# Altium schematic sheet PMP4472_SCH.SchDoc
size 431 x 279 mm; Date: Not shown in title block; ApprovedBy: Not shown in title block; CheckedBy: Not shown in title block; Author: Not shown in title block; CompanyName: Not shown in title block; Engineer: Not shown in title block; Organization: Not shown in title block; Address1: Not shown in title block; Address2: Not shown in title block; Address3: Not shown in title block; Address4: Not shown in title block; DocumentNumber: 1; Revision: Use project parameter SCH_Rev; SheetNumber: 1; SheetTotal: 1; PageSetup: Record=PageOptions¦CenterHorizontal=True¦CenterVertical=True¦PrintScale=1.00¦XCorrection=1.00¦YCorrection=1.00¦PrintKind=0¦BorderSize=5000000¦LeftOffset=0¦BottomOffset=0¦Orientation=2¦PaperLength=1000¦PaperWidth=1000¦Scale=100¦PaperSource=15¦PrintQuality=600¦MediaType=1¦DitherType=10¦PaperKind=Letter¦PrintScaleMode=1
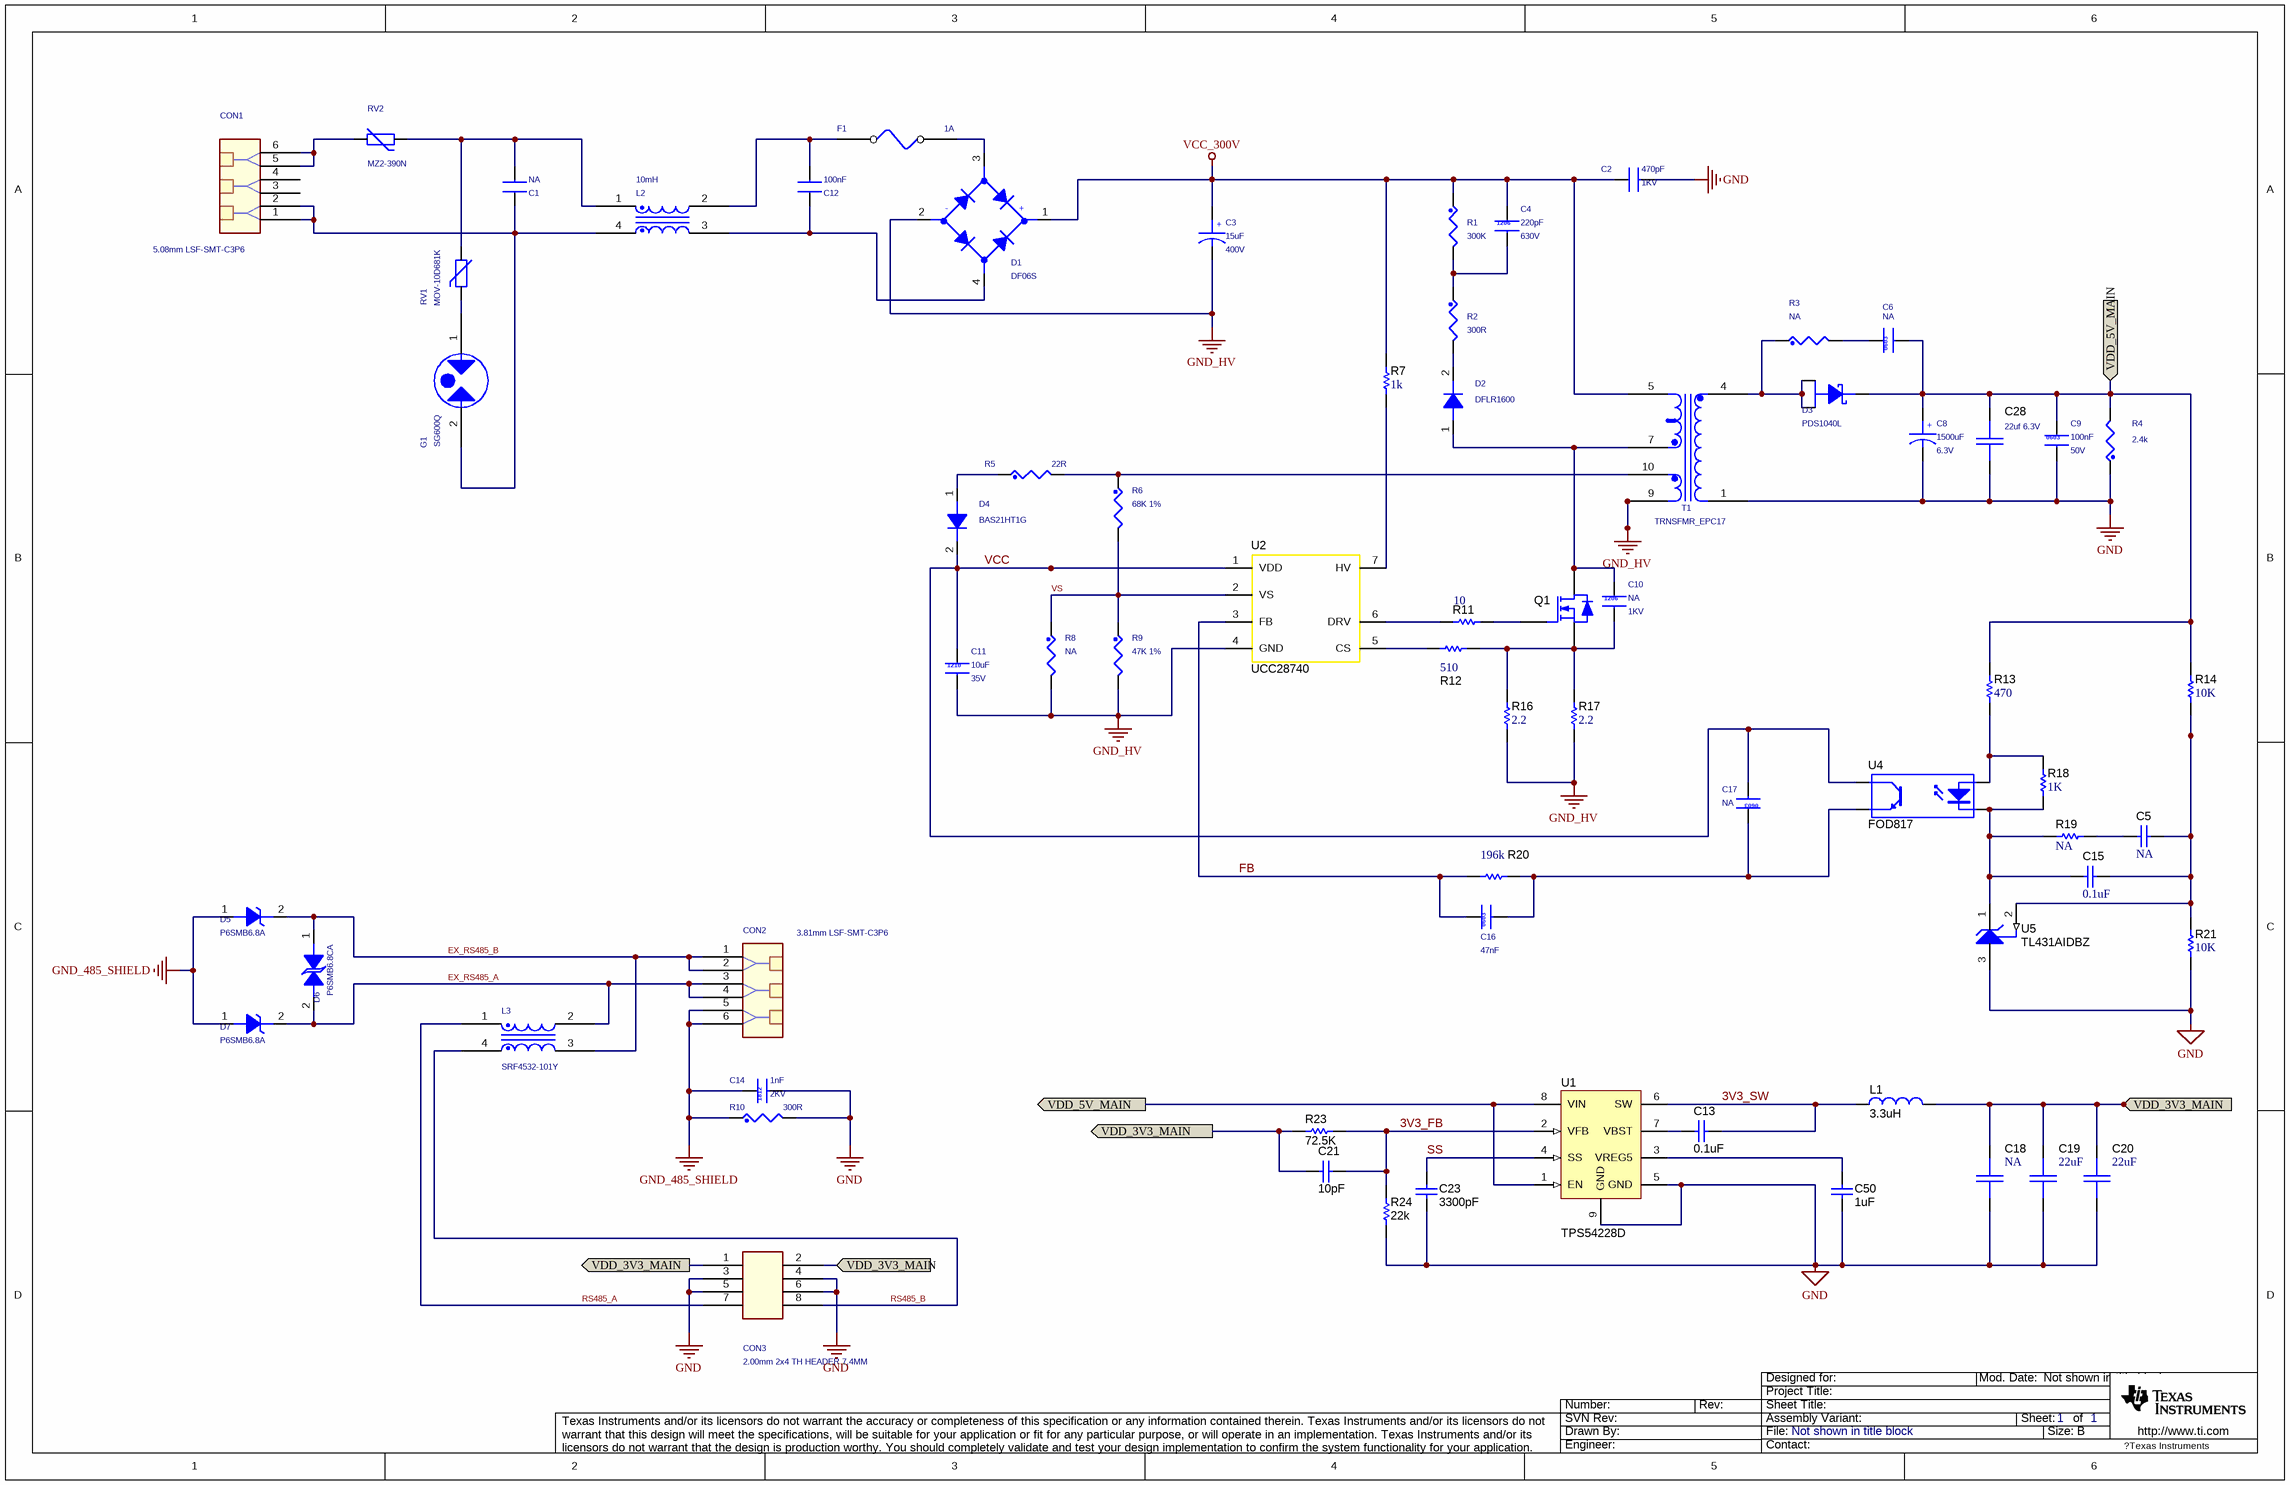
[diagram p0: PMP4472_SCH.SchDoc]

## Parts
C1  NA  [CAPRR_15D24_17D0X6D0X12D0]
C2  470pF  Voltage: 1KV  [CAPRR_10D16_9D5X7D0X9D5]
C3  15uF  Voltage: 400V  [CAPAE1000X1600_TH]
C4  220pF  Voltage: 630V  [C1206]
C5  value NA  [0603]  (hidden comment: Cap)
C6  NA  [C0603]
C8  1500uF  Voltage: 6.3V  [CAPAE1000X1600_TH]
C9  100nF  Voltage: 50V  [C0603]
C10  NA  Voltage: 1KV  [C1206]
C11  10uF  Voltage: 35V  [C1210]
C12  100nF  [CAPRR_15D24_17D0X6D0X12D0]
C13  ValueDisplayed: 0.1uF  [0603]  (hidden comment: 06031C331JAT2A)
C14  1nF  Voltage: 2KV  [C1812]
C15  value 0.1uF  [0603]  (hidden comment: Cap)
C16  47nF  [C0603]
C17  NA  [C0603]
C18  NA  [C1206]
C19  22uF  [C1206]
C20  22uF  [C1206]
C21  ValueDisplayed: 10pF  [0603]  (hidden comment: 06031C331JAT2A)
C23  ValueDisplayed: 3300pF  [0603]  (hidden comment: 06031C331JAT2A)
C28  22uf 6.3V  [C1206]
C50  ValueDisplayed: 1uF  [0603]  (hidden comment: 06031C331JAT2A)
CON1  5.08mm LSF-SMT-C3P6  [CON_LSF-SMT-5D08-C3P6-180]
CON2  3.81mm LSF-SMT-C3P6  [CON_LSF-SMT-3D81-C3P6-180]
CON3  2.00mm 2x4 TH HEADER 7.4MM  [CON_2D00_2X4_TH]
D1  DF06S  [DIODE_DFS]
D2  DFLR1600  [POWERDI123]
D3  PDS1040L  [POWERDI5]
D4  BAS21HT1G  [SOD-323]
D5  P6SMB6.8A  [SMB]
D6  P6SMB6.8CA  [SMB]
D7  P6SMB6.8A  [SMB]
F1  1A  [F5D08_8D5X4D0X8D0MM]
G1  SG600Q  [G4532]
L1  3.3uH  [Inductor 744778003]
L2  10mH  [L16D0X12D0X17D5MM]
L3  SRF4532-101Y  [L4D5X3D2X2D8MM]
Q1  (no value)  [TO-251AB]
R1  300K  [R1206]
R2  300R  [R1206]
R3  NA  [R0805]
R4  2.4k  [R1206]
R5  22R  [0603]
R6  68K 1%  [0603]
R7  value 1k  [0805]  (hidden comment: Res1)
R8  NA  [0603]
R9  47K 1%  [0603]
R10  300R  [R1206]
R11  value 10  [0603]  (hidden comment: Res1)
R12  value 510  [0603]  (hidden comment: Res1)
R13  value 470  [0603]  (hidden comment: Res1)
R14  value 10K  [0603]  (hidden comment: Res1)
R16  value 2.2  [0805]  (hidden comment: Res1)
R17  value 2.2  [0805]  (hidden comment: Res1)
R18  value 1K  [0603]  (hidden comment: Res1)
R19  value NA  [0603]  (hidden comment: Res1)
R20  value 196k  [0603]  (hidden comment: Res1)
R21  value 10K  [0603]  (hidden comment: Res1)
R23  value 72.5K  [0603]  (hidden comment: CRCW06031K00FKEA)
R24  value 22k  [0603]  (hidden comment: CRCW06031K00FKEA)
RV1  MOV-10D681K  [MOV-10D]
RV2  MZ2-390N  [PTC-T5MMD10MM]
T1  TRNSFMR_EPC17  [EPC17]
U1  TPS54228D  [DDA-8]
U2  UCC28740  [SOIC-7]
U4  FOD817  [OPTOCOUPLER]
U5  TL431AIDBZ  [SOT-23]

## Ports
VDD_3V3_MAIN, VDD_5V_MAIN

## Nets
GND: C2.2 C8.2 C9.2 C14.2 C18.1 C19.1 C20.1 C23.2 C28.1 C50.2 CON3.3 CON3.4 CON3.5 CON3.6 R4.1 R10.2 R21.1 R24.1 T1.1(OUT1_N) U1.5(GND) U1.9(GND) U5.3(ANODE)
GND_485_SHIELD: C14.1 CON2.5 CON2.6 D5.1(ANODE) D7.1(ANODE) R10.1
GND_HV: C3.2 C11.2 D1.2(DC_OUT_MINUS) R8.2 R9.2 R16.1 R17.1 T1.9(OUT1_N) U2.4(GND)
VCC_300V: C2.1 C3.1 C4.1 D1.1(DC_OUT_PLUS) R1.1 R7.2 T1.5(IN1)
3V3_FB: C21.1 R23.2 R24.2 U1.2(VFB)
3V3_SW: C13.1 L1.1 U1.6(SW)
EX_RS485_A: CON2.3 CON2.4 D6.2 D7.2(CATHODE) L3.2
EX_RS485_B: CON2.1 CON2.2 D5.2(CATHODE) D6.1 L3.3
FB: C16.1 R20.2 U2.3(FB)
RS485_A: CON3.7 L3.1
RS485_B: CON3.8 L3.4
SS: C23.1 U1.4(SS)
VCC: C11.1 C17.2 D4.2(K) U2.1(VDD) U4.4(C)
VDD_3V3_MAIN: C18.2 C19.2 C20.2 C21.2 CON3.1 CON3.2 L1.2 R23.1 ; port VDD_3V3_MAIN
VDD_5V_MAIN: C6.2 C8.1 C9.1 C28.2 D3.3(CATHODE) R4.2 R13.2 R14.2 U1.1(EN) U1.8(VIN) ; port VDD_5V_MAIN
VS: R6.2 R8.1 R9.1 U2.2(VS)
NetC1_1: C1.1 CON1.1 CON1.2 G1.2 L2.4
NetC1_2: C1.2 L2.1 RV1.1 RV2.2
NetC4_2: C4.2 R1.2 R2.1
NetC5_1: C5.1 C15.1 R14.1 R21.2 U5.2(REF)
NetC5_2: C5.2 R19.1
NetC6_1: C6.1 R3.2
NetC10_1: C10.1 D2.1(A) Q1.2(D) T1.7(IN2)
NetC10_2: C10.2 Q1.3(S) R12.2 R16.2 R17.2
NetC12_1: C12.1 D1.4(AC_IN_2) L2.3
NetC12_2: C12.2 F1.1 L2.2
NetC13_2: C13.2 U1.7(VBST)
NetC15_2: C15.2 R18.1 R19.2 U4.2(K) U5.1(CATHODE)
NetC16_2: C16.2 C17.1 R20.1 U4.3(E)
NetC50_1: C50.1 U1.3(VREG5)
NetCON1_5: CON1.5 CON1.6 RV2.1
NetD1_3: D1.3(AC_IN_1) F1.2
NetD2_2: D2.2(K) R2.2
NetD3_1: D3.1(ANODE1) D3.2(ANODE2) R3.1 T1.4(OUT2_P)
NetD4_1: D4.1(A) R5.1
NetG1_1: G1.1 RV1.2
NetQ1_1: Q1.1(G) R11.2
NetR5_2: R5.2 R6.1 T1.10(OUT1_P)
NetR7_1: R7.1 U2.7(HV)
NetR11_1: R11.1 U2.6(DRV)
NetR12_1: R12.1 U2.5(CS)
NetR13_1: R13.1 R18.2 U4.1(A)

Not connected (* = marked no-connect by the designer): CON1 3 4

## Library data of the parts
C1 C12 = CAP NP: CAP;100nF,CER,275V(UL CSA 250V),10%,CBB,17x6x12,TH; Manufacturer Part Number: RE104-L; Manufacturer: OKAYA; Part Number: 123020266
C2 = CAP NP: CAP;2.2nF,CER,1KV,5%,Z5U,9.5x7.0x9.5,TH; Part Number: 123020260; Manufacturer Part Number: CD90ZU2GA222MYNKA; Manufacturer: TDK
C3 = CAP POL: CAP;15uF,ALUM,400V,20%,ALUM,C10X16,DIP; Part Number: 123020270; Manufacturer Part Number: 400-AX-15-M-T8-10X16; Manufacturer: RUBYCON
C4 = CAP NP 1206: CAP;220pF,CER,630V,5%,COG,1206,SMD; Part Number: 123020262
C5 C15 = Cap: Capacitor
C6 C16 C17 = CAP NP 0603: CAP;1nF,CER,100V,10%,X7R,0603,SMD; Part Number: 123020148
C8 = CAP POL: CAP;1500uF,ALUM,6.3V,20%,ALUM,C10X12,DIP; Part Number: 123020272; Manufacturer Part Number: ORE152M0JBK-1012; Manufacturer: LELON
C9 = CAP NP 0603: CAP;100nF,CER,50V,10%,X7R,0603,SMD; Part Number: 123020218
C10 = CAP NP 1206: CAP;33pF,CER,1KV,5%,COG,1206,SMD; Part Number: 123020264
C11 = CAP NP 1210: CAP;10uF,CER,35V,10%,X5R,1210,SMD; Part Number: 123020098
C13 C21 C23 C50 = 06031C331JAT2A: CAP, CERM, 330pF, 100V, +5/%, X7R, 0603; Manufacturer: AVX; Polarized: N; CompType: Capacitor; U/M: EA; Cap_F: 0.00000000033; Tolerance_%: 5; ESR_Ohm: 0.472; Value1: 0.472 ohm; VDC_V: 100; TaMin_C: -55; TaMax_C: 125
C14 = CAP NP 1812: CAP;1nF,CER,2KV,10%,X7R,1812,SMD; Part Number: 123020160
C18-C20 C28 = C1206: Capacitor, Ceramic, 4V, X5R, 10%; MFR: Murata; Part Number: GRM31CR60G107ME39; Area: 15390
CON1 = LSF-SMT-C3P6: CONN HEADER;2x3P,5.08mm,VERT,DIP,LSF-SMT,TIN; Manufacturer: WEIDMULLER; Manufacturer Part Number: 1826060000; Part Number: 123050295
CON2 = LSF-SMT-C3P6: CONN HEADER;2x3P,3.81mm,VERT,DIP,LSF-SMT,TIN; Manufacturer: WEIDMULLER; Manufacturer Part Number: 1825800000; Part Number: 123050296
CON3 = CON8A: CONN HEADER;2x4P,2.00mm 7.4mm high,VERT,DIP,PIN,TIN; Part Number: 123050306
D1 = BRIDGE_SMD: BRIDGE;BRIDGE RECTIFIER,600V,1A,DFS,4PIN; Part Number: 126000056; Manufacturer: VISHAY
D2 = DIODE: DIODE;GLASS PASSIVATED,600V,1A,POWERDI123,SMD; Part Number: 123080088; Manufacturer Part Number: DFLR1600-7; Manufacturer: DIODES
D3 = DIODE POWERDI5: DIODE;SCHOTTKY,40V,10A,POWERDI5,SMD; Manufacturer: DIODES; Part Number: 123080090
D4 = DIODE: DIODE;HIGH VOLTAGE SWITCHING DIODE,250V,200mA,SOD323,SMD; Part Number: 123080089; Manufacturer: ON
D5 = DIODE TVS UNI-DIR: DIODE TVS;6.45V,7.14V,600W,UNI-DIR,SMA,SMD; Manufacturer: VISHAY; Part Number: 123080054
D6 = DIODE TVS BI-DIR: DIODE TVS;5.8V,6.8V,600W,BI-DIR,SMB,SMD; Part Number: 123080009; Manufacturer: VISHAY
D7 = DIODE TVS UNI-DIR: DIODE TVS;6.45V,7.14V,600W,UNI-DIR,SMA,SMD; Part Number: 123080054; Manufacturer: VISHAY
F1 = FUSE: FUSE;1A,250V,Time-Lag,8.5x4x8.0,TH; Manufacturer: LITTLEFUSE; Manufacturer Part Number: 39211000000; Part Number: 123090022
G1 = GDT_SINGLE: DIODES;gas discharge tube,-40C/+85C,SMD; Part Number: 123080092; Manufacturer: LITTLEFUSE
L1 = Inductor: Inductor, [Technology], [Material], xxuH, xxA, x.xx ohm, [MountType]; Manufacturer: Wurth; U/M: EA
L2 = COMMON MODE CHOKE CM14: IND;10mH,?,?mohm,1A,L16D0X12D0X17D5MM,TH; Part Number: 123030108
L3 = COMMON MODE CHOKE CM14: IND;2Kohm 10MHz,SRF4532-101Y,SMD,SHIELDED,FERRITE; Part Number: 123030103; Manufacturer: Bourns
Q1 = Mosfet: Manufacturer: Used in BOM report; SymbolVersion: use current date i.e. 2008-05-20; SymbolCreator: Use a-id; CompType: Used in some BOM reports.  Useful for finding later.; U/M: EA, IN, or GM
R1 = R: RES;300Kohm,1/4W,5%,1206,SMD; Part Number: 123010382
R2 R10 = R: RES;300ohm,1/4W,5%,1206,SMD; Part Number: 123010383
R3 = R: RES;15ohm,1/8W,5%,0805,SMD; Part Number: 123010384
R4 = R: RES;1.5Kohm,1/4W,5%,1206,SMD; Part Number: 123010291
R5 = R: RES;22ohm,1/10W,5%,0603,SMD; Part Number: 123010385
R6 R9 = R: RES;47Kohm,1/10W,1%,0603,SMD; Part Number: 123010391
R7 R11-R14 R16-R21 = Res1: Resistor
R8 = R: RES;360Kohm,1/10W,1%,0603,SMD; Part Number: 123010393
R23 R24 = CRCW06031K00FKEA: RES, 1.00k ohm, 1%, 0.1W, 0603; Manufacturer: Vishay-Dale; CompType: Resistor; Res_ohm: 1000; Value_Code: 1k00; Tolerance_%: 1; Power_W: 0.1; VDC_V: 75; TempCo: 100 ppm/C; EIA_Code: E96; U/M: EA
RV1 = VARISTOR_Dup1: MOV;MOV-10D681K,31V MOV,-40C/+85C,MOV-10D,2PIN; Manufacturer: BOURNS; Part Number: 123010389
RV2 = VARISTOR: PTC;MZ2-390N,,-40C/+85C,PTC-T5MMD10MM,2PIN; Manufacturer: 华中高理; Part Number: 123010394
T1 = TRNSFMR_EPC17: FLYBACK TRANSFORMER;8W,3.3V,2.2A,EPC17,TH,SHIELDED; Part Number: 123030112
U1 = TPS54228D: Buck Step Down Regulator with 4.5 to 18 V Input and 0.76 to 7 V Output, -40 to 85 degC, 8-Pin SOIC (D), Green (RoHS & no Sb/Br); Manufacturer: Texas Instruments; Alternate Manufacturer: None; Alternate PartNumber: Equivalent; Duty Cycle(Max)(%): 90; Iout(Max)(A): 2; Iq(Typ)(mA): 0.8; Rating: Catalog; Regulated Outputs(#): 1; SubFamily: Step-Down Regulator; Switch Current Limit(Typ)(A): 3.3; Synchronous Rectification: TRUE; Vin(Max)(V): 18; Vin(Min)(V): 4.5; Vout(Max)(V): 7; Vout(Min)(V): 0.76
U2 = UCC28740: Manufacturer: Used in BOM report; SymbolVersion: use current date i.e. 2008-05-20; SymbolCreator: Use a-id; CompType: Used in some BOM reports.  Useful for finding later.; U/M: EA, IN, or GM
U4 = Optoisolator1: 4-Pin Phototransistor Optocoupler
U5 = TL431AIDBZ: PRECISION PROGRAMMABLE REFERENCE, DBZ0003A; Alternate Manufacturer: None; Manufacturer: Texas Instruments; SymbolCreator: a0412235; CompType: IC; U/M: EA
